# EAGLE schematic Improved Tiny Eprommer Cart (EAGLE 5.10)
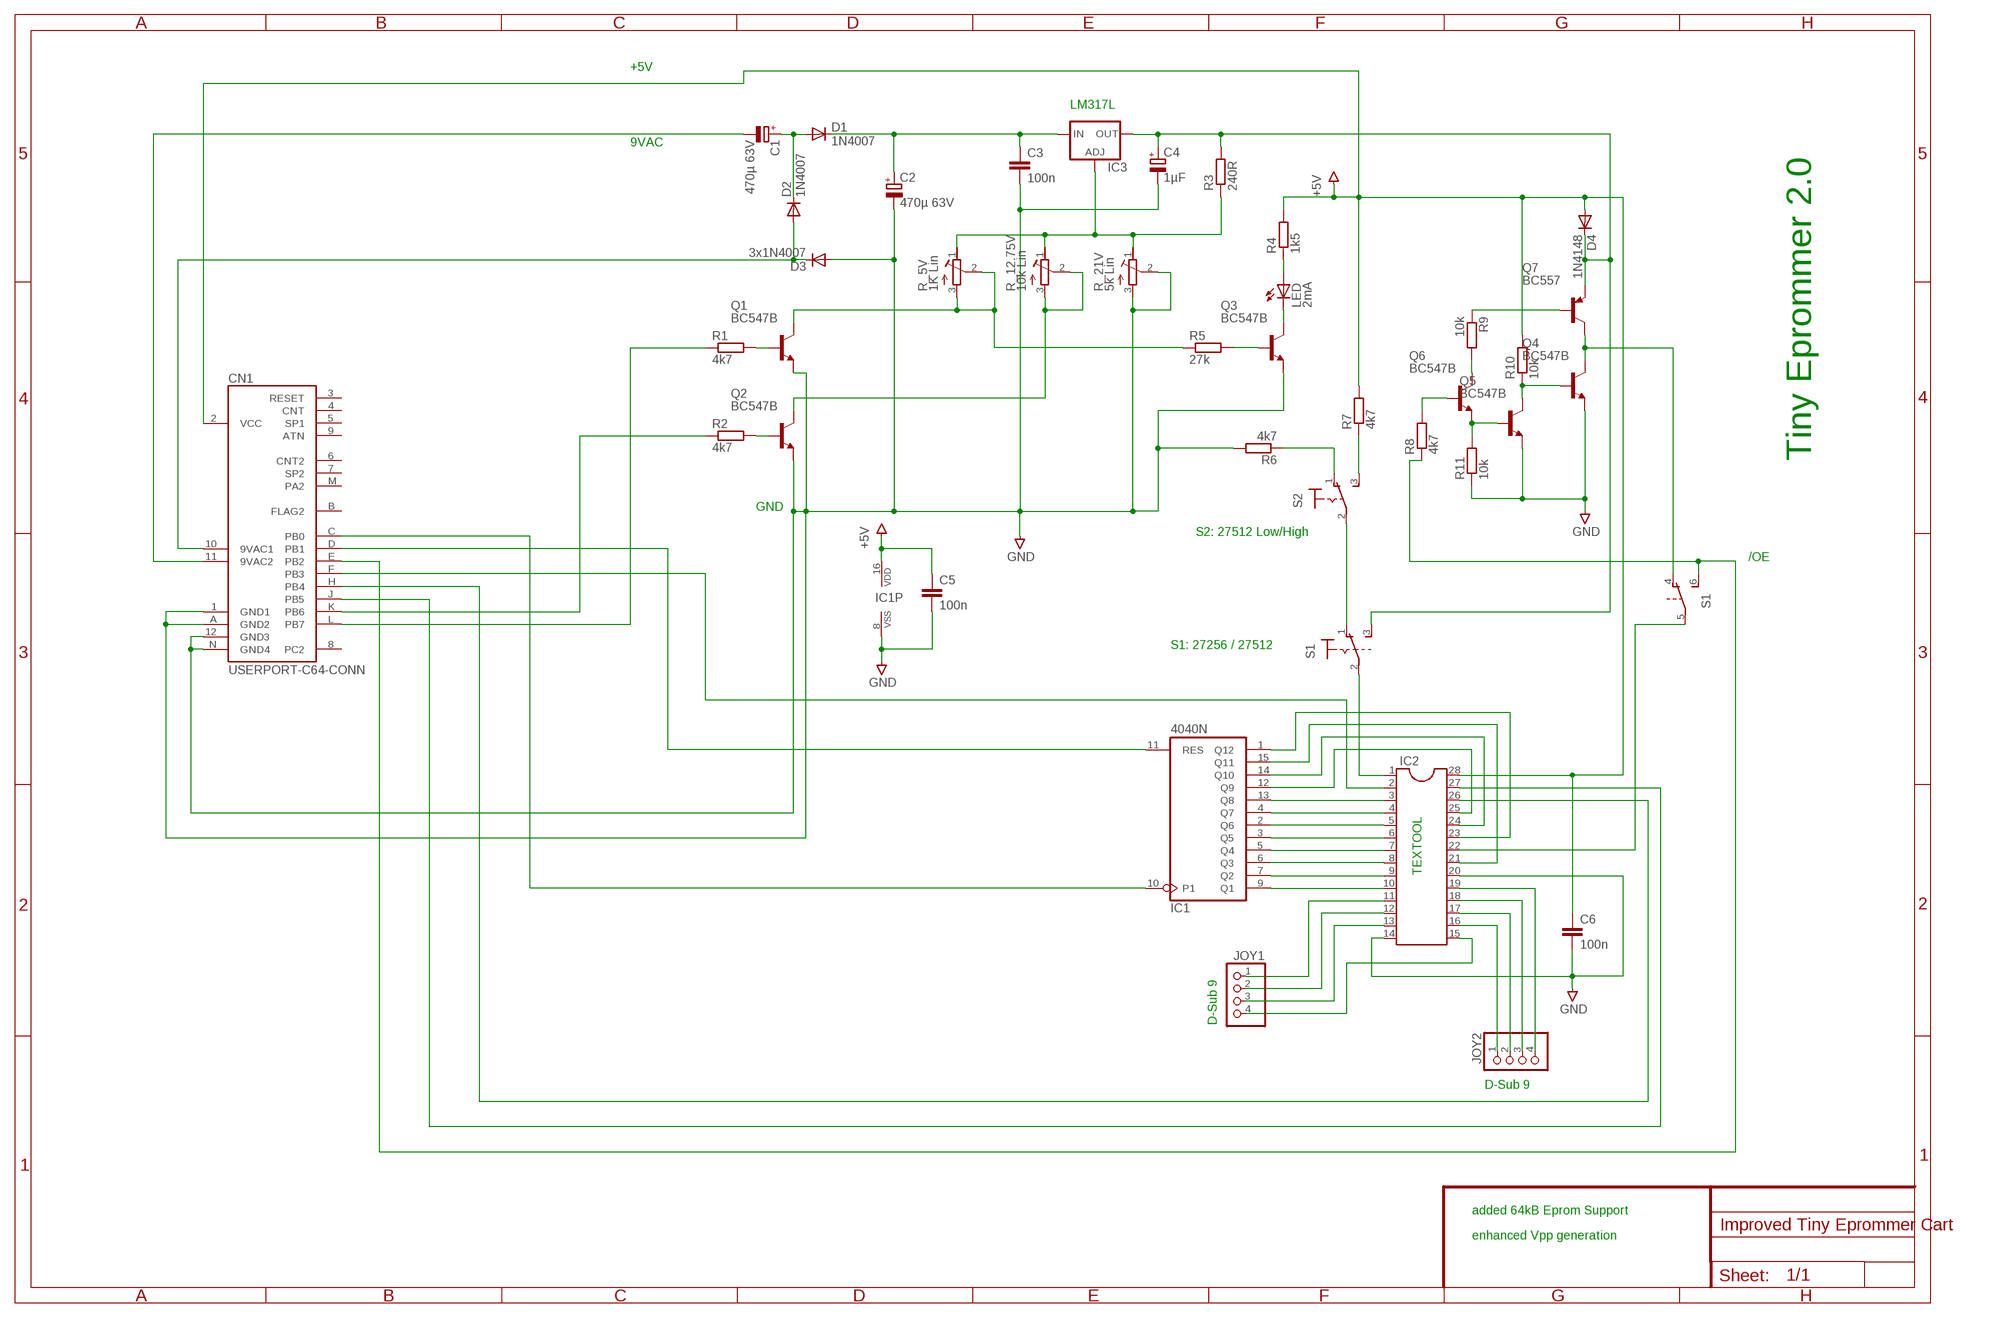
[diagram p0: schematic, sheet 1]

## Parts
C1  470µ 63V  CPOL-EUE5-13  [E5-13]
C2  470µ 63V  CPOL-EUE5-13  [E5-13]
C3  100n  C-EU050-025X075  [C050-025X075]
C4  1µF  CPOL-EUE5-6  [E5-6]
C5  100n  C-EU050-025X075  [C050-025X075]
C6  100n  C-EU050-025X075  [C050-025X075]
CN1  USERPORT-C64-CONN  [UPS24CONN]
D1  1N4007  1N4004  [DO41-10]
D2  1N4007  1N4004  [DO41-10]
D3  3x1N4007  1N4004  [DO41-10]
D4  1N4148  [DO35-10]
IC1  4040N  [DIL16]
IC2  DIL28  [DIL28-6]
IC3  LM317L  [317L]
JOY1  PINHD-1X4  [1X04]
JOY2  PINHD-1X4  [1X04]
LED  2mA  LED3MM  [LED3MM]
Q1  BC547B  [TO92]
Q2  BC547B  [TO92]
Q3  BC547B  [TO92]
Q4  BC547B  [TO92]
Q5  BC547B  [TO92]
Q6  BC547B  [TO92]
Q7  BC557  [TO92]
R1  4k7  R-EU_0207/7  [0207/7]
R2  4k7  R-EU_0207/7  [0207/7]
R3  240R  R-EU_0207/7  [0207/7]
R4  1k5  R-EU_0207/12  [0207/12]
R5  27k  R-EU_0207/7  [0207/7]
R6  4k7  R-EU_0207/7  [0207/7]
R7  4k7  R-EU_0207/7  [0207/7]
R8  4k7  R-EU_0207/7  [0207/7]
R9  10k  R-EU_0207/7  [0207/7]
R10  10k  R-EU_0207/7  [0207/7]
R11  10k  R-EU_0207/7  [0207/7]
R_5V  1K Lin  R-TRIMMT18  [RTRIMT18]
R_12.75V  10k Lin  R-TRIMMT18  [RTRIMT18]
R_21V  5k Lin  R-TRIMMT18  [RTRIMT18]
S1  M9040P2  [M9040P2]
S2  M9040P  [M9040P]

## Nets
+5V: C5.1 C6.1 CN1.2(VCC) D4.A IC1.16(VDD) IC2.28 R4.2 R7.2 R10.2
GND: C2.- C3.2 C4.- C5.2 C6.2 CN1.1(GND1) CN1.12(GND3) CN1.A(GND2) CN1.N(GND4) D3.A IC1.8(VSS) IC2.14 IC2.20 Q1.1(E) Q2.1(E) Q3.1(E) Q4.1(E) Q5.1(E) R6.2 R11.1 R_21V.2(S) R_21V.3(E)
N$1: IC2.22 S1.5(2:P)
N$2: IC2.1 S1.2(1:P)
N$3: S1.1(1:O) S2.2(P)
N$4: Q4.2(B) Q5.3(C) R10.1
N$5: C1.- CN1.11(9VAC2)
N$6: C1.+ D1.A D2.C
N$7: CN1.10(9VAC1) D2.A D3.C
N$9: C2.+ C3.1 D1.C IC3.3(IN)
N$10: R7.1 S2.3(S)
N$11: CN1.E(PB2) R8.1 S1.6(2:S)
N$12: IC3.1(ADJ) R3.1 R_5V.1(A) R_12.75V.1(A) R_21V.1(A)
N$13: LED.A R4.1
N$14: LED.K(C) Q3.3(C)
N$15: CN1.L(PB7) R1.1
N$16: Q1.2(B) R1.2
N$17: CN1.K(PB6) R2.1
N$18: Q2.2(B) R2.2
N$19: Q1.3(C) R5.1 R_5V.2(S) R_5V.3(E)
N$20: Q2.3(C) R_12.75V.2(S) R_12.75V.3(E)
N$21: IC1.9(Q1) IC2.10
N$22: Q3.2(B) R5.2
N$23: R6.1 S2.1(O)
N$24: CN1.C(PB0) IC1.10(P1)
N$25: CN1.D(PB1) IC1.11(RES)
N$26: IC1.7(Q2) IC2.9
N$27: IC1.6(Q3) IC2.8
N$28: IC1.5(Q4) IC2.7
N$29: IC1.3(Q5) IC2.6
N$30: IC1.2(Q6) IC2.5
N$31: IC1.4(Q7) IC2.4
N$32: IC1.13(Q8) IC2.3
N$33: IC1.12(Q9) IC2.25
N$34: IC1.14(Q10) IC2.24
N$35: IC1.15(Q11) IC2.21
N$36: IC1.1(Q12) IC2.23
N$37: CN1.F(PB3) IC2.2
N$38: CN1.J(PB5) IC2.27
N$39: CN1.H(PB4) IC2.26
N$40: Q4.3(C) Q7.3(C) S1.4(2:O)
N$41: IC2.13 JOY1.3
N$42: IC2.12 JOY1.2
N$43: IC2.11 JOY1.1
N$44: IC2.15 JOY1.4
N$45: Q5.2(B) Q6.1(E) R11.2
N$46: IC2.16 JOY2.1
N$47: IC2.17 JOY2.2
N$48: IC2.18 JOY2.3
N$49: IC2.19 JOY2.4
N$50: Q6.3(C) R9.2
N$51: Q7.2(B) R9.1
N$52: Q6.2(B) R8.2
VPP: C4.+ D4.C IC3.2(OUT) Q7.1(E) R3.2 S1.3(1:S)
Unconnected: CN1.3(RESET) CN1.4(CNT) CN1.5(SP1) CN1.6(CNT2) CN1.7(SP2) CN1.8(PC2) CN1.9(ATN) CN1.B(FLAG2) CN1.M(PA2)

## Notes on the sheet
- +5V
- LM317L
- 9VAC
- Tiny Eprommer 2.0
- GND
- S2: 27512 Low/High
- /OE
- S1: 27256 / 27512
- TEXTOOL
- D-Sub 9
- D-Sub 9
- added 64kB Eprom Support
- enhanced Vpp generation

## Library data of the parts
C1 C2 C4 = rcl:CPOL-EU: POLARIZED CAPACITOR, European symbol
C3 C5 C6 = rcl:C-EU: CAPACITOR, European symbol
CN1 = 0RB_Commodore:USERPORT-C64-CONN
D1-D3 = diode:1N4004: DIODE
D4 = diode:1N4148: DIODE
IC1 = 40xx:4040: 12-stage binary/ripple COUNTER
IC2 = ic-package:DIL28: Dual In Line
IC3 = v-reg:LM317L: VOLTAGE REGULATOR
JOY1 JOY2 = pinhead:PINHD-1X4: PIN HEADER
LED = led:LED: LED
Q1-Q6 = transistor-npn:BC547*: NPN Transistor
Q7 = transistor-pnp:BC557: PNP Transistor
R1-R11 = rcl:R-EU_: RESISTOR, European symbol
R_5V R_12.75V R_21V = rcl:R-TRIMM: Trimm resistor
S1 = switch:M9040P2: TOGGLE SWITCH Marquardt
S2 = switch:M9040P: TOGGLE SWITCH Marquardt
